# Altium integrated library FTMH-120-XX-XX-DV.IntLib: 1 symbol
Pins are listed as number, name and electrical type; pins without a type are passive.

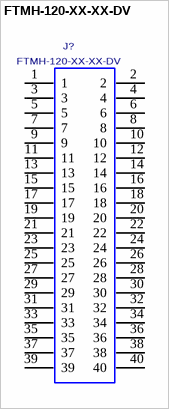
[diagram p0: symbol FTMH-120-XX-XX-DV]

## FTMH-120-XX-XX-DV
designator J?
1MM PITCH, 40PINS, TERMINAL STRIP; MANUFACTURER: SAMTEC
footprint FTMH-120-XX-XX-DV
pins: 1, 2, 3, 4, 5, 6, 7, 8, 9, 10, 11, 12, 13, 14, 15, 16, 17, 18, 19, 20, 21, 22, 23, 24, 25, 26, 27, 28, 29, 30, 31, 32, 33, 34, 35, 36, 37, 38, 39, 40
